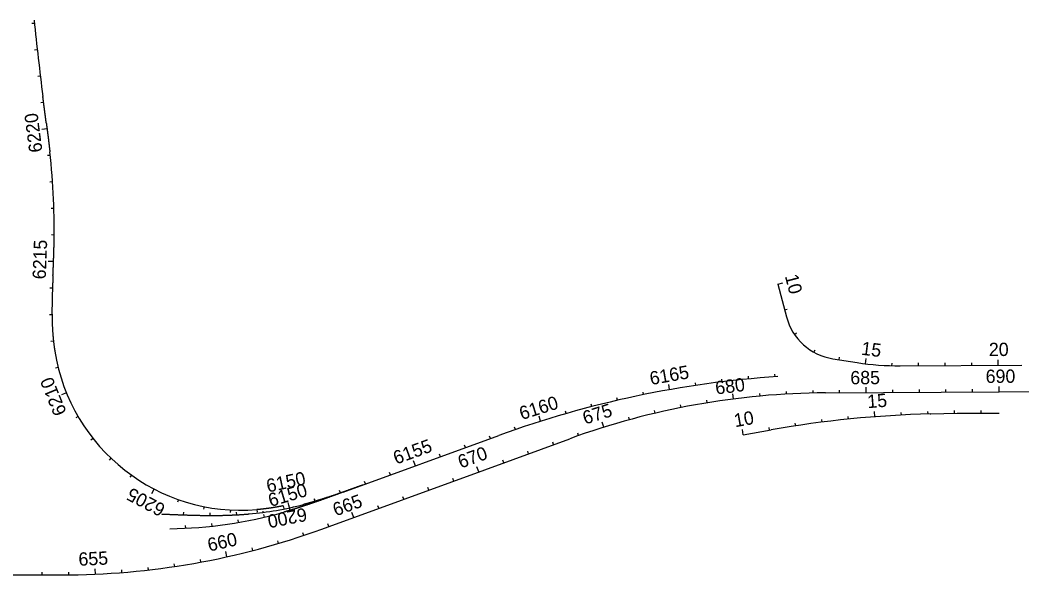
# Model space of a CAD drawing. Extents: x 448091 to 665917, y 1461380 to 1587607.
# Drawn here: x 533497 to 537266, y 1527494 to 1529581 of the extents above; entities that cross this region are included whole.
import ezdxf

# ---------------------------------------------------------------- set-up
doc = ezdxf.new("R2010")
doc.units = 0
doc.layers.add('TextShtNo', color=7, linetype='Continuous')
doc.layers.add('TextTitle', color=7, linetype='Continuous')

msp = doc.modelspace()

# ---------------------------------------------------------------- linework, layer by layer
at = {"layer": 'TextShtNo'}
for p, q in [((536347.8, 1528588), (536380.2, 1528465.1)), ((536554.8, 1528307.5), (536646.7, 1528293.1)), ((536807.9, 1528281.1), (537266.2, 1528283.9)), ((536527.1, 1528179.3), (537180, 1528183.4)), ((537180, 1528183.4), (537888.9, 1528187.8)), ((536922, 1528099.9), (537022, 1528102.4)), ((537022, 1528102.4), (537180.5, 1528103.4)), ((536217.9, 1528021.4), (536323.1, 1528040)), ((534712, 1527805.7), (535298.1, 1528019)), ((535245.3, 1527890.2), (535565.1, 1528006.6)), ((534632.6, 1527667.2), (535245.3, 1527890.2)), ((533106, 1527494.5), (533652.8, 1527494.5))]:
    msp.add_line(p, q, dxfattribs=at)
for centre, radius, start, end in [((544943.6, 1530733.2), 11451.6, 185.77389, 187.21886), ((530925.5, 1528789.5), 2700, 358.7368, 6.3019), ((536588.1, 1528519.9), 215, 194.7758, 261.0862), ((534329, 1528447.5), 710, 189.0692, 274.7823), ((536801.7, 1529281), 1000, 261.0862, 270.3567), ((536604.5, 1524429.6), 3819.7, 93.8497, 109.9994), ((536544.9, 1525314.6), 2864.8, 90.3567, 109.9994), ((537019.6, 1524101.1), 4000, 91.3983, 100.0268), ((534041.2, 1529305.2), 1637, 270.6906, 285.8869), ((534248.1, 1528969), 1250, 275.0929, 284.6136), ((533652.8, 1530359.2), 2864.8, 269.9994, 289.9994)]:
    msp.add_arc(centre, radius, start, end, dxfattribs=at)
for points in [[(533595.6, 1529195), (533595.4, 1529196.3), (533595.2, 1529197.7), (533595.1, 1529199), (533594.9, 1529200.4), (533594.7, 1529201.7), (533594.5, 1529203), (533594.4, 1529204.4), (533594.2, 1529205.7), (533594, 1529207.1), (533593.8, 1529208.4), (533593.7, 1529209.7), (533593.5, 1529211.1), (533593.3, 1529212.4), (533593.1, 1529213.8), (533593, 1529215.1), (533592.8, 1529216.4), (533592.6, 1529217.8), (533592.4, 1529219.1), (533592.3, 1529220.5), (533592.1, 1529221.8), (533591.9, 1529223.1), (533591.7, 1529224.5), (533591.6, 1529225.8), (533591.4, 1529227.2), (533591.2, 1529228.5), (533591, 1529229.8), (533590.9, 1529231.2), (533590.7, 1529232.5), (533590.5, 1529233.9), (533590.3, 1529235.2), (533590.2, 1529236.5), (533590, 1529237.9), (533589.8, 1529239.2), (533589.6, 1529240.6), (533589.5, 1529241.9), (533589.3, 1529243.2), (533589.1, 1529244.6), (533588.9, 1529245.9), (533588.8, 1529247.3), (533588.6, 1529248.6), (533588.4, 1529249.9), (533588.2, 1529251.3), (533588.1, 1529252.6), (533587.9, 1529254), (533587.7, 1529255.3), (533587.6, 1529256.6), (533587.4, 1529258), (533587.2, 1529259.3), (533587, 1529260.7), (533586.9, 1529262), (533586.7, 1529263.3), (533586.5, 1529264.7), (533586.3, 1529266), (533586.2, 1529267.4), (533586, 1529268.7), (533585.8, 1529270), (533585.7, 1529271.4), (533585.5, 1529272.7), (533585.3, 1529274.1), (533585.1, 1529275.4), (533585, 1529276.8), (533584.8, 1529278.1), (533584.6, 1529279.4), (533584.5, 1529280.8), (533584.3, 1529282.1), (533584.1, 1529283.5), (533583.9, 1529284.8), (533583.8, 1529286.1), (533583.6, 1529287.5), (533583.4, 1529288.8), (533583.3, 1529290.2), (533583.1, 1529291.5), (533582.9, 1529292.8), (533582.7, 1529294.2)], [(533595.6, 1529195), (533595.8, 1529193.5), (533596, 1529192.1), (533596.2, 1529190.6), (533596.4, 1529189.1), (533596.6, 1529187.6), (533596.8, 1529186.2), (533597, 1529184.7), (533597.1, 1529183.2), (533597.3, 1529181.7), (533597.5, 1529180.3), (533597.7, 1529178.8), (533597.9, 1529177.3), (533598.1, 1529175.8), (533598.3, 1529174.4), (533598.5, 1529172.9), (533598.7, 1529171.4), (533598.9, 1529170), (533599.1, 1529168.5), (533599.3, 1529167), (533599.5, 1529165.5), (533599.6, 1529164.1), (533599.8, 1529162.6), (533600, 1529161.1), (533600.2, 1529159.6), (533600.4, 1529158.2), (533600.6, 1529156.7), (533600.8, 1529155.2), (533601, 1529153.7), (533601.2, 1529152.3), (533601.3, 1529150.8), (533601.5, 1529149.3), (533601.7, 1529147.8), (533601.9, 1529146.4), (533602.1, 1529144.9), (533602.3, 1529143.4), (533602.5, 1529141.9), (533602.7, 1529140.5), (533602.8, 1529139), (533603, 1529137.5), (533603.2, 1529136), (533603.4, 1529134.6), (533603.6, 1529133.1), (533603.8, 1529131.6), (533603.9, 1529130.1), (533604.1, 1529128.7), (533604.3, 1529127.2), (533604.5, 1529125.7), (533604.7, 1529124.2), (533604.9, 1529122.8), (533605, 1529121.3), (533605.2, 1529119.8), (533605.4, 1529118.3), (533605.6, 1529116.9), (533605.7, 1529115.4), (533605.9, 1529113.9), (533606.1, 1529112.4), (533606.3, 1529111), (533606.5, 1529109.5), (533606.6, 1529108), (533606.8, 1529106.5), (533607, 1529105), (533607.1, 1529103.6), (533607.3, 1529102.1), (533607.5, 1529100.6), (533607.7, 1529099.1), (533607.8, 1529097.7), (533608, 1529096.2), (533608.2, 1529094.7), (533608.3, 1529093.2), (533608.5, 1529091.8), (533608.7, 1529090.3), (533608.8, 1529088.8), (533609, 1529087.3), (533609.2, 1529085.8)], [(533620.9, 1528620), (533621, 1528621.5), (533621, 1528623), (533621.1, 1528624.5), (533621.2, 1528626), (533621.2, 1528627.5), (533621.3, 1528628.9), (533621.3, 1528630.4), (533621.4, 1528631.9), (533621.5, 1528633.4), (533621.5, 1528634.9), (533621.6, 1528636.4), (533621.7, 1528637.8), (533621.7, 1528639.3), (533621.8, 1528640.8), (533621.8, 1528642.3), (533621.9, 1528643.8), (533622, 1528645.3), (533622, 1528646.8), (533622.1, 1528648.2), (533622.1, 1528649.7), (533622.2, 1528651.2), (533622.3, 1528652.7), (533622.3, 1528654.2), (533622.4, 1528655.7), (533622.4, 1528657.2), (533622.5, 1528658.6), (533622.6, 1528660.1), (533622.6, 1528661.6), (533622.7, 1528663.1), (533622.7, 1528664.6), (533622.8, 1528666.1), (533622.9, 1528667.6), (533622.9, 1528669), (533623, 1528670.5), (533623, 1528672), (533623.1, 1528673.5), (533623.1, 1528675), (533623.2, 1528676.5), (533623.2, 1528678), (533623.3, 1528679.4), (533623.4, 1528680.9), (533623.4, 1528682.4), (533623.5, 1528683.9), (533623.5, 1528685.4), (533623.6, 1528686.9), (533623.6, 1528688.4), (533623.7, 1528689.8), (533623.7, 1528691.3), (533623.8, 1528692.8), (533623.8, 1528694.3), (533623.9, 1528695.8), (533623.9, 1528697.3), (533624, 1528698.8), (533624, 1528700.2), (533624.1, 1528701.7), (533624.1, 1528703.2), (533624.2, 1528704.7), (533624.2, 1528706.2), (533624.2, 1528707.7), (533624.3, 1528709.2), (533624.3, 1528710.6), (533624.4, 1528712.1), (533624.4, 1528713.6), (533624.5, 1528715.1), (533624.5, 1528716.6), (533624.5, 1528718.1), (533624.6, 1528719.6), (533624.6, 1528721), (533624.6, 1528722.5), (533624.7, 1528724), (533624.7, 1528725.5), (533624.8, 1528727), (533624.8, 1528728.5), (533624.8, 1528730)], [(533620.9, 1528620), (533620.7, 1528616.2), (533620.6, 1528612.3), (533620.4, 1528608.5), (533620.2, 1528604.6), (533620.1, 1528600.8), (533619.9, 1528596.9), (533619.8, 1528593.1), (533619.6, 1528589.2), (533619.5, 1528585.4), (533619.3, 1528581.5), (533619.2, 1528577.7), (533619, 1528573.8), (533618.9, 1528570), (533618.7, 1528566.2), (533618.6, 1528562.3), (533618.5, 1528558.5), (533618.4, 1528554.6), (533618.2, 1528550.8), (533618.1, 1528546.9), (533618, 1528543.1), (533617.9, 1528539.2), (533617.8, 1528535.4), (533617.7, 1528531.5), (533617.6, 1528527.7), (533617.6, 1528523.8), (533617.5, 1528520), (533617.4, 1528516.1), (533617.4, 1528512.3), (533617.3, 1528508.4), (533617.3, 1528504.5), (533617.2, 1528500.7), (533617.2, 1528496.8), (533617.2, 1528493), (533617.2, 1528489.1), (533617.2, 1528485.3), (533617.2, 1528481.4), (533617.2, 1528477.6), (533617.3, 1528473.7), (533617.3, 1528469.9), (533617.4, 1528466), (533617.4, 1528462.2), (533617.5, 1528458.3), (533617.6, 1528454.5), (533617.7, 1528450.6), (533617.8, 1528446.8), (533618, 1528442.9), (533618.1, 1528439.1), (533618.3, 1528435.2), (533618.4, 1528431.4), (533618.6, 1528427.5), (533618.8, 1528423.7), (533619, 1528419.9), (533619.2, 1528416), (533619.5, 1528412.2), (533619.7, 1528408.3), (533620, 1528404.5), (533620.3, 1528400.6), (533620.6, 1528396.8), (533620.9, 1528393), (533621.3, 1528389.1), (533621.6, 1528385.3), (533622, 1528381.5), (533622.4, 1528377.6), (533622.8, 1528373.8), (533623.2, 1528370), (533623.6, 1528366.1), (533624.1, 1528362.3), (533624.6, 1528358.5), (533625.1, 1528354.7), (533625.6, 1528350.9), (533626.1, 1528347), (533626.7, 1528343.2), (533627.3, 1528339.4), (533627.9, 1528335.6)], [(534712, 1527805.7), (534709, 1527804.6), (534706, 1527803.5), (534703, 1527802.5), (534700, 1527801.4), (534697.1, 1527800.3), (534694.1, 1527799.2), (534691.1, 1527798.1), (534688.1, 1527797), (534685.1, 1527795.9), (534682.1, 1527794.9), (534679.1, 1527793.8), (534676.2, 1527792.7), (534673.2, 1527791.6), (534670.2, 1527790.5), (534667.2, 1527789.5), (534664.2, 1527788.4), (534661.2, 1527787.3), (534658.2, 1527786.2), (534655.2, 1527785.2), (534652.3, 1527784.1), (534649.3, 1527783), (534646.3, 1527782), (534643.3, 1527780.9), (534640.3, 1527779.8), (534637.3, 1527778.8), (534634.3, 1527777.7), (534631.3, 1527776.6), (534628.3, 1527775.6), (534625.3, 1527774.5), (534622.3, 1527773.5), (534619.3, 1527772.4), (534616.3, 1527771.4), (534613.3, 1527770.3), (534610.3, 1527769.3), (534607.3, 1527768.3), (534604.3, 1527767.2), (534601.3, 1527766.2), (534598.3, 1527765.2), (534595.3, 1527764.1), (534592.3, 1527763.1), (534589.3, 1527762.1), (534586.3, 1527761.1), (534583.3, 1527760), (534580.3, 1527759), (534577.3, 1527758), (534574.3, 1527757), (534571.2, 1527756), (534568.2, 1527755), (534565.2, 1527754), (534562.2, 1527753), (534559.2, 1527752.1), (534556.2, 1527751.1), (534553.1, 1527750.1), (534550.1, 1527749.1), (534547.1, 1527748.2), (534544.1, 1527747.2), (534541, 1527746.2), (534538, 1527745.3), (534535, 1527744.3), (534531.9, 1527743.4), (534528.9, 1527742.4), (534525.9, 1527741.5), (534522.8, 1527740.6), (534519.8, 1527739.6), (534516.8, 1527738.7), (534513.7, 1527737.8), (534510.7, 1527736.9), (534507.6, 1527736), (534504.6, 1527735.1), (534501.5, 1527734.2), (534498.5, 1527733.3), (534495.4, 1527732.4), (534492.4, 1527731.5), (534489.3, 1527730.7)], [(534786.6, 1527832.9), (534783.6, 1527831.8), (534780.6, 1527830.7), (534777.7, 1527829.6), (534774.7, 1527828.5), (534771.7, 1527827.4), (534768.7, 1527826.4), (534765.7, 1527825.3), (534762.7, 1527824.2), (534759.7, 1527823.1), (534756.8, 1527822), (534753.8, 1527821), (534750.8, 1527819.9), (534747.8, 1527818.8), (534744.8, 1527817.7), (534741.8, 1527816.6), (534738.8, 1527815.6), (534735.8, 1527814.5), (534732.9, 1527813.4), (534729.9, 1527812.4), (534726.9, 1527811.3), (534723.9, 1527810.2), (534720.9, 1527809.2), (534717.9, 1527808.1), (534714.9, 1527807), (534711.9, 1527806), (534708.9, 1527804.9), (534705.9, 1527803.9), (534702.9, 1527802.8), (534699.9, 1527801.8), (534696.9, 1527800.8), (534693.9, 1527799.7), (534690.9, 1527798.7), (534687.9, 1527797.6), (534684.9, 1527796.6), (534681.9, 1527795.6), (534678.9, 1527794.6), (534675.9, 1527793.6), (534672.9, 1527792.5), (534669.9, 1527791.5), (534666.9, 1527790.5), (534663.8, 1527789.5), (534660.8, 1527788.5), (534657.8, 1527787.5), (534654.8, 1527786.5), (534651.8, 1527785.6), (534648.8, 1527784.6), (534645.7, 1527783.6), (534642.7, 1527782.6), (534639.7, 1527781.7), (534636.7, 1527780.7), (534633.6, 1527779.8), (534630.6, 1527778.8), (534627.6, 1527777.9), (534624.5, 1527776.9), (534621.5, 1527776), (534618.5, 1527775.1), (534615.4, 1527774.1), (534612.4, 1527773.2), (534609.3, 1527772.3), (534606.3, 1527771.4), (534603.2, 1527770.5), (534600.2, 1527769.6), (534597.1, 1527768.7), (534594.1, 1527767.9), (534591, 1527767), (534588, 1527766.1), (534584.9, 1527765.3), (534581.9, 1527764.4), (534578.8, 1527763.6), (534575.7, 1527762.8), (534572.7, 1527761.9), (534569.6, 1527761.1), (534566.5, 1527760.3), (534563.5, 1527759.5)], [(534029.3, 1527723.7), (534033.8, 1527723.5), (534038.2, 1527723.3), (534042.7, 1527723.1), (534047.1, 1527722.9), (534051.6, 1527722.7), (534056, 1527722.5), (534060.5, 1527722.4), (534064.9, 1527722.2), (534069.4, 1527722), (534073.9, 1527721.8), (534078.3, 1527721.6), (534082.8, 1527721.4), (534087.2, 1527721.3), (534091.7, 1527721.1), (534096.1, 1527720.9), (534100.6, 1527720.8), (534105.1, 1527720.6), (534109.5, 1527720.4), (534114, 1527720.3), (534118.4, 1527720.1), (534122.9, 1527720), (534127.3, 1527719.8), (534131.8, 1527719.7), (534136.3, 1527719.6), (534140.7, 1527719.4), (534145.2, 1527719.3), (534149.6, 1527719.2), (534154.1, 1527719.1), (534158.5, 1527719), (534163, 1527718.9), (534167.5, 1527718.8), (534171.9, 1527718.7), (534176.4, 1527718.6), (534180.8, 1527718.6), (534185.3, 1527718.5), (534189.8, 1527718.4), (534194.2, 1527718.4), (534198.7, 1527718.4), (534203.1, 1527718.3), (534207.6, 1527718.3), (534212, 1527718.3), (534216.5, 1527718.3), (534221, 1527718.3), (534225.4, 1527718.3), (534229.9, 1527718.3), (534234.3, 1527718.3), (534238.8, 1527718.4), (534243.3, 1527718.4), (534247.7, 1527718.5), (534252.2, 1527718.6), (534256.6, 1527718.6), (534261.1, 1527718.7), (534265.6, 1527718.8), (534270, 1527719), (534274.5, 1527719.1), (534278.9, 1527719.2), (534283.4, 1527719.4), (534287.8, 1527719.5), (534292.3, 1527719.7), (534296.8, 1527719.9), (534301.2, 1527720.1), (534305.7, 1527720.3), (534310.1, 1527720.5), (534314.6, 1527720.8), (534319, 1527721), (534323.5, 1527721.3), (534327.9, 1527721.6), (534332.4, 1527721.9), (534336.8, 1527722.2), (534341.3, 1527722.5), (534345.7, 1527722.9), (534350.2, 1527723.2), (534354.6, 1527723.6), (534359, 1527724)], [(534487.1, 1527754.3), (534485.8, 1527754.1), (534484.4, 1527753.8), (534483.1, 1527753.6), (534481.8, 1527753.3), (534480.5, 1527753.1), (534479.1, 1527752.8), (534477.8, 1527752.5), (534476.5, 1527752.3), (534475.1, 1527752.1), (534473.8, 1527751.8), (534472.5, 1527751.6), (534471.2, 1527751.3), (534469.8, 1527751.1), (534468.5, 1527750.8), (534467.2, 1527750.6), (534465.8, 1527750.4), (534464.5, 1527750.1), (534463.2, 1527749.9), (534461.8, 1527749.7), (534460.5, 1527749.4), (534459.2, 1527749.2), (534457.8, 1527749), (534456.5, 1527748.8), (534455.2, 1527748.5), (534453.9, 1527748.3), (534452.5, 1527748.1), (534451.2, 1527747.9), (534449.8, 1527747.7), (534448.5, 1527747.4), (534447.2, 1527747.2), (534445.8, 1527747), (534444.5, 1527746.8), (534443.2, 1527746.6), (534441.8, 1527746.4), (534440.5, 1527746.2), (534439.2, 1527746), (534437.8, 1527745.8), (534436.5, 1527745.6), (534435.2, 1527745.4), (534433.8, 1527745.2), (534432.5, 1527745), (534431.1, 1527744.8), (534429.8, 1527744.7), (534428.5, 1527744.5), (534427.1, 1527744.3), (534425.8, 1527744.1), (534424.4, 1527743.9), (534423.1, 1527743.8), (534421.8, 1527743.6), (534420.4, 1527743.4), (534419.1, 1527743.2), (534417.7, 1527743.1), (534416.4, 1527742.9), (534415.1, 1527742.8), (534413.7, 1527742.6), (534412.4, 1527742.4), (534411, 1527742.3), (534409.7, 1527742.1), (534408.3, 1527742), (534407, 1527741.8), (534405.7, 1527741.7), (534404.3, 1527741.5), (534403, 1527741.4), (534401.6, 1527741.3), (534400.3, 1527741.1), (534398.9, 1527741), (534397.6, 1527740.9), (534396.3, 1527740.7), (534394.9, 1527740.6), (534393.6, 1527740.5), (534392.2, 1527740.4), (534390.9, 1527740.2), (534389.5, 1527740.1), (534388.2, 1527740)]]:
    msp.add_spline(points, degree=3, dxfattribs=at)
at = {"layer": 'TextTitle'}
for p, q in [((533551.3, 1529568.7), (533541.4, 1529567.7)), ((533561.9, 1529469.3), (533552, 1529468.2)), ((533573.4, 1529370), (533563.5, 1529368.8)), ((533585.7, 1529270.7), (533575.8, 1529269.5)), ((533598.7, 1529171.6), (533578.8, 1529169)), ((533610.6, 1529072.3), (533600.7, 1529071.2)), ((533619.3, 1528972.7), (533609.3, 1528972)), ((533624.2, 1528872.8), (533614.2, 1528872.5)), ((533625.4, 1528772.8), (533615.4, 1528772.9)), ((533623.1, 1528672.8), (533603.1, 1528673.6)), ((536347.8, 1528588), (536367.1, 1528593.1)), ((533619, 1528572.9), (533609, 1528573.3)), ((536373.3, 1528491.3), (536383, 1528493.9)), ((533617.3, 1528472.9), (533607.3, 1528472.8)), ((536410.3, 1528399.1), (536418.6, 1528404.7)), ((533622.8, 1528373.1), (533612.9, 1528372.1)), ((536483.4, 1528332.2), (536488.2, 1528340.9)), ((536578.6, 1528303.8), (536580.1, 1528313.7)), ((536677.4, 1528288.8), (536679.9, 1528308.6)), ((536777.1, 1528281.3), (536777.4, 1528291.3)), ((536877.1, 1528281.5), (536877, 1528291.5)), ((536977.1, 1528282.1), (536977, 1528292.1)), ((537077.1, 1528282.7), (537077, 1528292.7)), ((537177.1, 1528283.4), (537177, 1528303.4)), ((533640.3, 1528274.8), (533630.6, 1528272.3)), ((536039.5, 1528207.4), (536038.1, 1528217.3)), ((536138.6, 1528220.9), (536137.4, 1528230.8)), ((536238, 1528231.8), (536237.1, 1528241.7)), ((536337.7, 1528240), (536337, 1528250)), ((533671.4, 1528179.8), (533652.9, 1528172.3)), ((535842.6, 1528172.6), (535840.6, 1528182.4)), ((535940.8, 1528191.3), (535937.4, 1528211)), ((536181.3, 1528156.2), (536178.7, 1528176)), ((536280.7, 1528167.2), (536279.7, 1528177.1)), ((536380.4, 1528174.6), (536379.8, 1528184.6)), ((536480.3, 1528178.6), (536480.1, 1528188.6)), ((536580.3, 1528179.6), (536580.2, 1528189.6)), ((536680.3, 1528180.3), (536680.2, 1528200.3)), ((536780.3, 1528180.9), (536780.2, 1528190.9)), ((536880.3, 1528181.5), (536880.2, 1528191.5)), ((536980.3, 1528182.1), (536980.2, 1528192.1)), ((537080.3, 1528182.8), (537080.2, 1528192.8)), ((537180.3, 1528183.4), (537180.2, 1528203.4)), ((535647.8, 1528127.6), (535645.3, 1528137.3)), ((535744.9, 1528151.4), (535742.6, 1528161.1)), ((536082.3, 1528141.8), (536080.7, 1528151.6)), ((535551.3, 1528101.3), (535548.5, 1528110.9)), ((535886.2, 1528102.6), (535883.9, 1528112.4)), ((535983.9, 1528123.9), (535982, 1528133.7)), ((536713, 1528089.4), (536711.5, 1528109.3)), ((536812.8, 1528095.8), (536812.3, 1528105.8)), ((536912.8, 1528099.7), (536912.5, 1528109.7)), ((537012.7, 1528102.2), (537012.5, 1528112.3)), ((537112.7, 1528103), (537112.7, 1528113)), ((533715.5, 1528090.1), (533706.9, 1528085.1)), ((535455.5, 1528072.5), (535449.5, 1528091.6)), ((535693.4, 1528049.9), (535687.4, 1528069)), ((535789.3, 1528077.9), (535786.7, 1528087.6)), ((536415.1, 1528055.2), (536413.6, 1528065.1)), ((536514.1, 1528069.1), (536512.8, 1528079)), ((536613.4, 1528080.5), (536612.4, 1528090.4)), ((535360.6, 1528041.2), (535357.3, 1528050.6)), ((535598.4, 1528018.5), (535595.1, 1528027.9)), ((536217.9, 1528021.4), (536214.5, 1528041.1)), ((536316.4, 1528038.9), (536314.7, 1528048.7)), ((533771.7, 1528007.6), (533763.9, 1528001.4)), ((535266.4, 1528007.5), (535263, 1528016.9)), ((535504.4, 1527984.5), (535501, 1527993.9)), ((535172.4, 1527973.3), (535169, 1527982.7)), ((535410.4, 1527950.3), (535407, 1527959.7)), ((533839, 1527933.7), (533832.1, 1527926.5)), ((534984.5, 1527904.9), (534977.7, 1527923.7)), ((535078.5, 1527939.1), (535075, 1527948.5)), ((535316.4, 1527916.1), (535313, 1527925.5)), ((534890.5, 1527870.7), (534887.1, 1527880.1)), ((535222.5, 1527881.9), (535215.6, 1527900.7)), ((533916, 1527870), (533910.2, 1527861.9)), ((534796.6, 1527836.5), (534793.1, 1527845.9)), ((535128.5, 1527847.7), (535125.1, 1527857.1)), ((534001.2, 1527817.7), (533991.9, 1527800)), ((534702.4, 1527802.7), (534699.3, 1527811.7)), ((534702.6, 1527802.3), (534700.9, 1527807)), ((535034.5, 1527813.5), (535031.1, 1527822.9)), ((534092.8, 1527778), (534089.5, 1527768.5)), ((534510.5, 1527746.9), (534506.3, 1527766.5)), ((534607.4, 1527771.7), (534604.5, 1527781.3)), ((534608.4, 1527768.6), (534605.1, 1527778.1)), ((534940.6, 1527779.3), (534937.1, 1527788.7)), ((534112.5, 1527720.3), (534112.9, 1527730.3)), ((534189.2, 1527751.4), (534187.2, 1527741.6)), ((534212.5, 1527718.3), (534212.5, 1527728.3)), ((534288.3, 1527738.7), (534287.7, 1527728.7)), ((534312.5, 1527720.7), (534311.9, 1527730.7)), ((534388.2, 1527740), (534389, 1527730)), ((534412, 1527729.8), (534411.4, 1527734.8)), ((534487.1, 1527754.3), (534489, 1527744.5)), ((534513.3, 1527737.7), (534507.6, 1527756.8)), ((534752.6, 1527710.9), (534745.8, 1527729.7)), ((534846.6, 1527745.1), (534843.2, 1527754.5)), ((534219.8, 1527677.9), (534218.7, 1527687.8)), ((534318.8, 1527691.8), (534317.1, 1527701.7)), ((534416.8, 1527711.8), (534414.5, 1527721.5)), ((534658.6, 1527676.7), (534655.2, 1527686.1)), ((534120.1, 1527670), (534119.6, 1527680)), ((534564.4, 1527643.3), (534561.2, 1527652.8)), ((534469, 1527613.2), (534466.2, 1527622.8)), ((534275.5, 1527562.9), (534271.1, 1527582.5)), ((534372.7, 1527586.4), (534370.2, 1527596.1)), ((534078.9, 1527526.3), (534077.4, 1527536.2)), ((534177.5, 1527542.9), (534175.7, 1527552.7)), ((533580.5, 1527494.5), (533580.5, 1527504.5)), ((533680.5, 1527494.6), (533680.4, 1527504.6)), ((533780.5, 1527497.3), (533779.6, 1527517.3)), ((533880.3, 1527503.5), (533879.5, 1527513.5)), ((533979.8, 1527513.2), (533978.6, 1527523.1))]:
    msp.add_line(p, q, dxfattribs=at)
msp.add_circle((536922, 1528099.9), 0.8, dxfattribs=at)

# ---------------------------------------------------------------- texts
for s, rotation, p in [('6220', 97.4151, (533581.7, 1529086.4)), ('6215', 87.8392, (533593.7, 1528605.6)), ('10', 284.7758, (536373.9, 1528618.3)), ('15', 352.8638, (536659.8, 1528322.7)), ('20', 0.3567, (537141.8, 1528317.4)), ('6165', 10.0049, (535870.4, 1528208.4)), ('685', 0.3567, (536620.6, 1528211.3)), ('690', 0.3567, (537129.8, 1528216.4)), ('6210', 112.1538, (533673.4, 1528105.7)), ('680', 7.2923, (536115.7, 1528172.6)), ('15', 4.3948, (536686.3, 1528121.5)), ('6160', 17.5049, (535384.6, 1528076.7)), ('675', 17.2923, (535622.6, 1528059.6)), ('10', 10.0268, (536187.6, 1528049.9)), ('6155', 19.9994, (534912, 1527909.3)), ('670', 19.9994, (535155.3, 1527894.3)), ('6150', 12.1192, (534429.6, 1527804.1)), ('6150', 16.7154, (534439.5, 1527749.7)), ('6205', 152.503, (534047.9, 1527755.9)), ('665', 19.9994, (534684.6, 1527714.5)), ('6200', 191.1312, (534570.7, 1527747.7)), ('660', 12.5539, (534208.6, 1527582.2)), ('655', 2.5539, (533717.9, 1527528.7))]:
    msp.add_text(s, height=50, rotation=rotation, dxfattribs=at).set_placement(p)

doc.saveas('drawing.dxf')
